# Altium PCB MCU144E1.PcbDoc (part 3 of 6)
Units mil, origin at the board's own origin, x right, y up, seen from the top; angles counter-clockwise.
Board outline 2755.9 x 2276.49 mil, 10 copper layers (Top Layer, L02_GND1, L03_SIG1, L04_GND2, L05_SIG2, L06_PWR, L07_GND3, L08_SIG3, L09_GND4, Bottom Layer), stack 60.4 mil thick; 257 components, 312 nets, 1297 pads, 831 vias.
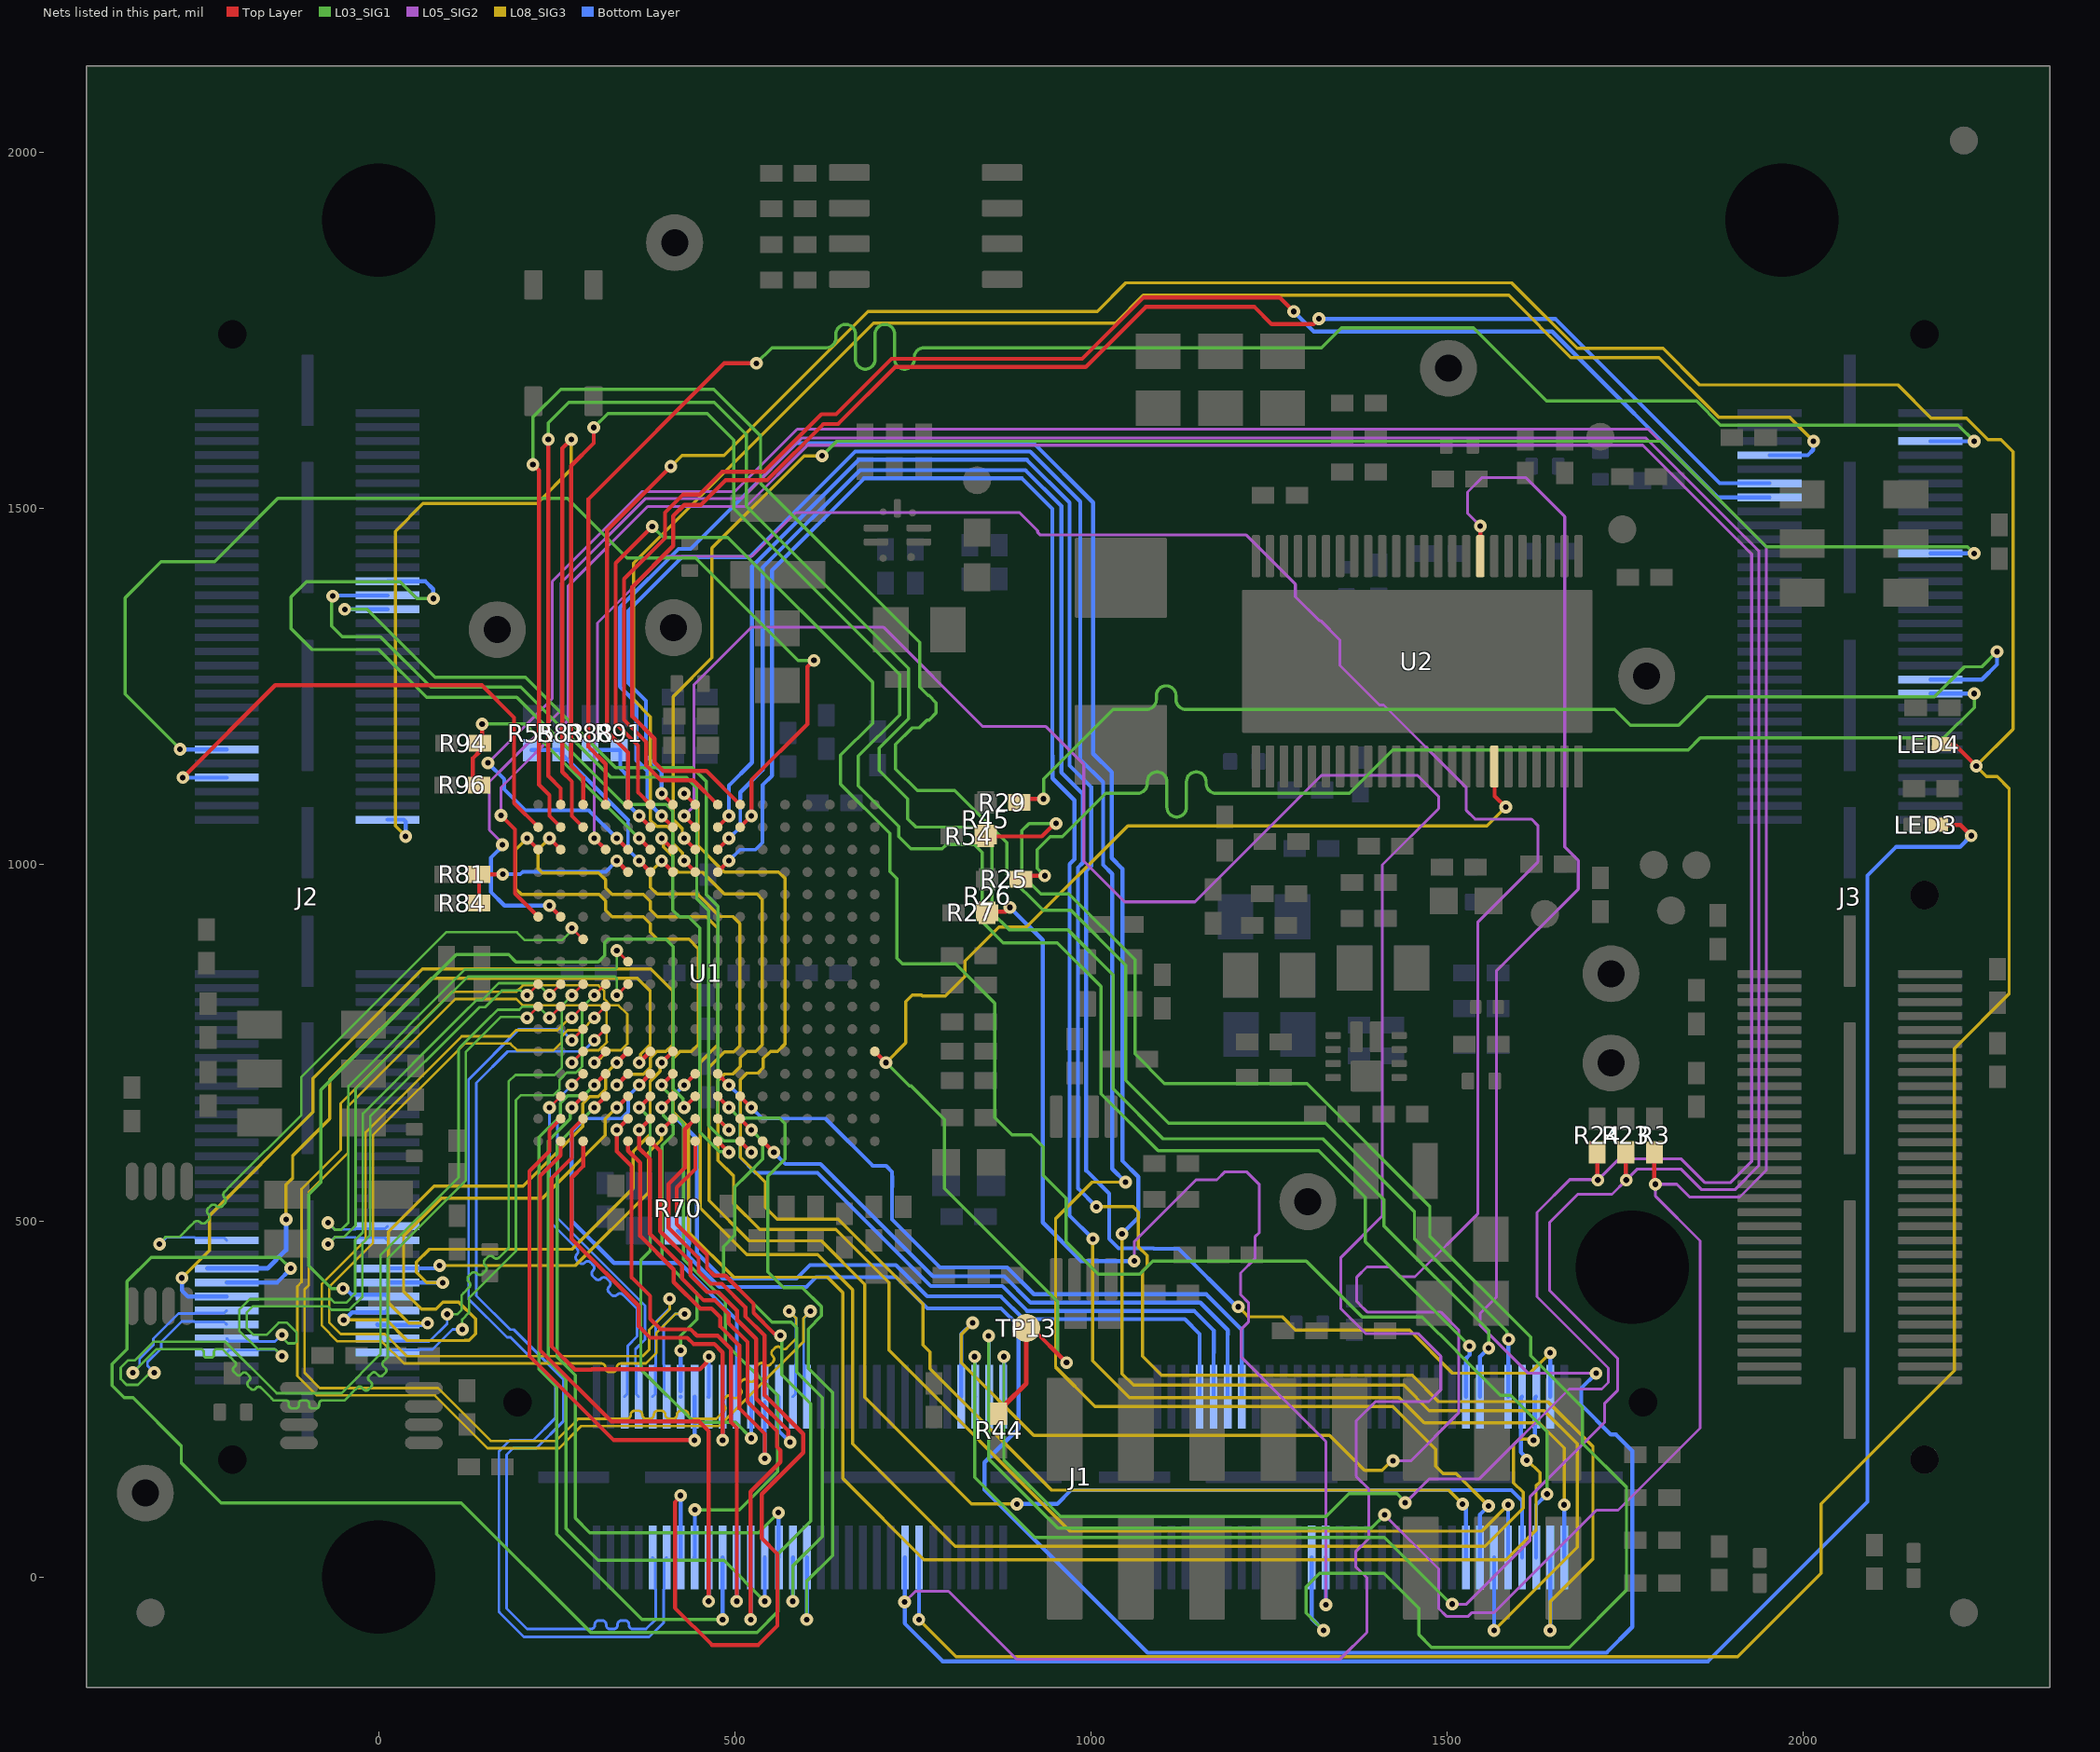
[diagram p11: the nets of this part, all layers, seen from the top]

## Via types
v1: diameter 18, hole 8, Top Layer to Bottom Layer, tented both sides, 777 vias
v2: diameter 19.68, hole 7.87, Top Layer to Bottom Layer, tented top, 54 vias

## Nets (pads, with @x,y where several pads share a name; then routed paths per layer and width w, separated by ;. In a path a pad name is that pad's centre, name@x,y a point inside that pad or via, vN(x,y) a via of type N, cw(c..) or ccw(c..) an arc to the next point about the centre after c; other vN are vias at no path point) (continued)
MCU_ADCIN_A10A11_P: J2.100 U1.G3 | length 960.5
  Top Layer w3.7: v1(271.28,911.2) U1.G3@287.03,895.46
  L03_SIG1 w3.5: v1(-307.61,467.54) -307.61,469.18 -299.35,477.44 -279.7,477.44 -271.97,485.17 -266.24,490.9 -258.8,498.35 cw(c-254.79,494.34) -250.78,498.35 -250.45,498.02 ccw(c-246.44,502.03) -242.43,498.02 -239,501.46 ccw(c-243.01,505.47) -239,509.48 -239.32,509.8 cw(c-235.31,513.81) -239.32,517.82 -235.89,521.26 cw(c-231.88,517.25) -227.87,521.26 -227.54,520.93 ccw(c-223.53,524.94) -219.52,520.93 -216.09,524.37 ccw(c-220.1,528.38) -216.09,532.39 -216.41,532.71 cw(c-212.4,536.72) -216.41,540.73 -208.07,549.07 -108.46,648.68 -108.46,702.12 94.74,905.33 159.9,905.33 193.9,905.33 204.94,894.29 257.51,894.29 274.42,911.2 v1(271.28,911.2)
  Bottom Layer w3.7: v1(-307.61,467.54) -298.11,477.04 -269.75,477.04 -258.53,477.04 -257.69,476.2 -216.69,476.2 J2.100@-213.19,472.7
MCU_ADCIN_A12A13_N: J2.110 U1.K1 | length 1321.3
  Top Layer w3.7: v1(208.29,785.22) U1.K1@224.04,800.97
  L03_SIG1 w3.5: v1(-345,287) -312,320 -278.92,320 -266.81,320 -259.71,320 -249.77,320 cw(c-249.77,315.74) -245.51,315.74 -245.51,312.26 ccw(c-241.25,312.26) -241.25,308 -235.57,308 ccw(c-235.57,312.26) -231.31,312.26 -231.31,315.74 cw(c-227.05,315.74) -227.05,320 -219.42,320 -213.57,314.15 -208.55,309.13 -201.52,302.1 cw(c-204.54,299.09) -201.52,296.07 -203.28,294.32 ccw(c-200.27,291.31) -203.28,288.3 -199.26,284.28 ccw(c-196.25,287.29) -193.24,284.28 -191.48,286.03 cw(c-188.47,283.02) -185.46,286.03 -181.44,282.02 cw(c-184.45,279.01) -181.44,275.99 -183.2,274.24 ccw(c-180.18,271.23) -183.2,268.21 -179.18,264.2 ccw(c-176.17,267.21) -173.16,264.2 -171.4,265.95 cw(c-168.39,262.94) -165.38,265.95 -165.13,265.7 -150.35,250.93 -147.36,247.94 -140.26,247.94 -130.32,247.94 cw(c-130.32,243.68) -126.06,243.68 -126.06,241.2 ccw(c-121.8,241.2) -121.8,236.94 -116.12,236.94 ccw(c-116.12,241.2) -111.86,241.2 -111.86,243.68 cw(c-107.6,243.68) -107.6,247.94 -101.92,247.94 cw(c-101.92,243.68) -97.66,243.68 -97.66,241.2 ccw(c-93.4,241.2) -93.4,236.94 -87.72,236.94 ccw(c-87.72,241.2) -83.46,241.2 -83.46,243.68 cw(c-79.2,243.68) -79.2,247.94 -69.26,247.94 -65,247.94 -48.61,247.94 -47.89,247.94 -41.67,254.16 -36.65,259.18 -29.62,266.21 cw(c-26.61,263.19) -23.6,266.21 -20.43,263.04 ccw(c-17.42,266.05) -14.4,263.04 -10.39,267.05 ccw(c-13.4,270.07) -10.39,273.08 -13.55,276.25 cw(c-10.54,279.26) -13.55,282.27 -9.54,286.29 cw(c-6.53,283.28) -3.51,286.29 -0.35,283.12 ccw(c2.67,286.13) 5.68,283.12 9.7,287.14 ccw(c6.68,290.15) 9.7,293.16 6.53,296.33 cw(c9.54,299.34) 6.53,302.35 10.04,305.87 12.82,308.64 12.82,447.24 122.4,556.82 122.4,737.4 171.36,786.36 198.5,786.36 199.65,785.22 v1(208.29,785.22)
  Bottom Layer w3.7: v1(-345,287) -335.5,296.5 -335.5,306.34 -316.2,325.63 -316.2,334.58 -280.86,369.93 -258.53,369.93 -257.69,370.77 -216.69,370.77 J2.110@-213.19,374.27
MCU_ADCIN_A12A13_P: J2.112 U1.K2 | length 1321.6
  Top Layer w3.7: v1(239.79,785.22) U1.K2@255.53,800.97
  L03_SIG1 w3.5: v1(-315,287) -320.82,287 -337.92,269.9 -353.9,269.9 -362.1,278.1 -362.1,294.08 -352.08,304.1 -342.32,304.1 -316.22,330.2 -215.2,330.2 -143.14,258.14 -52.11,258.14 2.62,312.87 2.62,451.47 112.2,561.05 112.2,741.62 115.09,744.51 151.16,780.58 167.14,796.56 197.57,796.56 201.98,800.97 224.04,800.97 v1(239.79,785.22)
  Bottom Layer w3.7: v1(-315,287) -324.5,296.5 -324.5,301.78 -305.2,321.08 -305.2,330.03 -276.3,358.93 -258.53,358.93 -257.69,358.09 -216.69,358.09 J2.112@-213.19,354.59
MCU_ADCIN_A14A15_N: J1.90 U1.M4 | length 2014.2
  Top Layer w3.7: v1(302.78,722.23) U1.M4@318.53,737.98
  L08_SIG3 w3.5: v1@298.55,722.23 v1(302.78,722.23) 304.94,722.23 311.53,728.81 ; 311.99,728.36 323.25,739.62 340.11,739.62 349.09,748.6 349.09,790.34 336.82,802.62 325.78,802.62 316.88,811.52 316.88,822.56 308.62,830.82 202.45,830.82 193.48,821.85 103.42,821.85 -53.29,665.13 -53.29,599.71 -108.2,544.8 -108.2,414.22 -114.2,408.22 -114.2,282.37 -86.83,255 79,255 153,181 253.42,181 284.42,212 478,212 596.38,330.38 596.38,363.33 v1(606.28,373.23)
  Bottom Layer w3.7: J1.90@597.62,252.13 597.47,252.28 597.47,297.81 596.78,298.51 596.78,363.73 v1(606.28,373.23)
MCU_ADCIN_A14A15_P: J1.92 U1.M3 | length 2055.5
  Top Layer w3.7: v1(271.28,722.23) U1.M3@287.03,737.98
  L08_SIG3 w3.5: v1(271.28,722.23) 288.68,739.62 308.83,739.62 320,750.79 ; 320.17,752.11 320.17,750.97 320,750.79 ; v1(576.28,373.23) 586.18,363.33 586.18,334.6 573.01,321.43 cw(c569,325.44) 564.99,321.43 564.52,321.9 ccw(c560.51,317.89) 556.5,321.9 553.07,318.46 ccw(c557.08,314.45) 553.07,310.44 553.53,309.98 cw(c549.52,305.97) 553.53,301.96 550.1,298.52 cw(c546.09,302.53) 542.08,298.52 541.61,298.99 ccw(c537.6,294.98) 533.59,298.99 530.16,295.55 ccw(c534.16,291.54) 530.16,287.53 530.62,287.07 cw(c526.61,283.06) 530.62,279.05 527.19,275.61 cw(c523.18,279.62) 519.17,275.61 518.7,276.08 ccw(c514.69,272.07) 510.68,276.08 507.25,272.64 ccw(c511.25,268.63) 507.25,264.62 507.71,264.16 cw(c503.7,260.15) 507.71,256.14 504.28,252.7 cw(c500.27,256.71) 496.26,252.7 495.79,253.17 ccw(c491.78,249.16) 487.77,253.17 484.33,249.73 ccw(c488.34,245.72) 484.33,241.71 484.8,241.25 cw(c480.79,237.24) 484.8,233.23 473.78,222.2 440.54,222.2 cw(c440.54,227.87) 434.87,227.87 ccw(c429.2,227.87) 429.2,233.54 424.34,233.54 ccw(c424.34,227.87) 418.67,227.87 cw(c413,227.87) 413,222.2 408.14,222.2 cw(c408.14,227.87) 402.47,227.87 ccw(c396.8,227.87) 396.8,233.54 391.94,233.54 ccw(c391.94,227.87) 386.27,227.87 cw(c380.6,227.87) 380.6,222.2 375.74,222.2 cw(c375.74,227.87) 370.07,227.87 ccw(c364.4,227.87) 364.4,233.54 359.54,233.54 ccw(c359.54,227.87) 353.87,227.87 cw(c348.2,227.87) 348.2,222.2 280.2,222.2 249.2,191.2 157.22,191.2 83.22,265.2 -82.6,265.2 -104,286.6 -104,404 -98,410 -98,540.57 -46.08,592.49 -43.09,595.48 -43.09,660.91 107.65,811.65 193.35,811.65 202.38,802.62 311.35,802.62 320,793.97 320,750.79
  Bottom Layer w3.7: v1(576.28,373.23) 585.78,363.73 585.78,298.53 584.94,297.69 J1.92@584.94,256.69 ; J1.92@581.44,253.19 J1.92@584.94,256.69 ; 585.78,298.51 585.09,297.81 585.09,256.84 J1.92@584.94,256.69
MCU_ADCIN_B0B1_N: J1.114 U1.N3 | length 526.7
  Top Layer w3.7: v1(271.28,690.73) U1.N3@287.03,706.48
  Bottom Layer w3.7: v1(271.28,690.73) 255.53,674.98 255.53,643.41 250.74,638.61 250.74,504.26 373.89,381.11 373.89,333.34 360.56,320.01 360.56,298.53 361.4,297.69 361.4,256.69 J1.114@364.9,253.19
MCU_ADCIN_B0B1_P: J1.116 U1.P2 | length 527.2
  Top Layer w3.7: v1(239.79,659.24) U1.P2@255.53,674.98
  Bottom Layer w3.7: 239.74,627.36 239.74,499.71 271.38,468.07 278.42,461.02 cw(c274.46,457.06) 278.42,453.1 278.16,452.84 ccw(c282.12,448.88) 278.16,444.92 281.55,441.53 ccw(c285.51,445.49) 289.47,441.53 289.73,441.79 cw(c293.69,437.83) 297.65,441.79 301.05,438.4 cw(c297.09,434.44) 301.05,430.48 300.79,430.22 ccw(c304.75,426.26) 300.79,422.3 304.18,418.9 ccw(c308.14,422.86) 312.1,418.9 312.36,419.16 cw(c316.32,415.2) 320.28,419.16 323.67,415.77 cw(c319.71,411.81) 323.67,407.85 323.41,407.59 ccw(c327.37,403.63) 323.41,399.67 326.81,396.28 ccw(c330.77,400.24) 334.73,396.28 334.99,396.54 cw(c338.95,392.58) 342.91,396.54 344.6,394.84 362.89,376.55 362.89,337.9 349.56,324.57 349.56,298.53 348.72,297.69 348.72,256.69 J1.116@345.22,253.19 ; 239.79,627.36 v1(239.79,659.24)
MCU_ADCIN_B2B3_N: J1.109 U1.L3 | length 1403.2
  Top Layer w3.7: v1(271.28,753.72) U1.L3@287.03,769.47
  Bottom Layer w3.7: v1(271.28,753.72) 255.69,769.32 197.02,769.32 126.21,698.5 126.21,390.41 180.15,336.47 185.15,336.47 248.04,273.58 248.04,223.16 216.99,192.12 184.36,192.12 168.74,176.5 168.74,-48.74 171.96,-51.96 204,-84 380,-84 399.93,-64.07 399.93,-17.75 400.77,-16.91 400.77,24.09 J1.109@404.27,27.59
MCU_ADCIN_B2B3_P: J1.111 U1.L4 | length 1400.5
  Top Layer w3.7: v1(302.78,753.72) U1.L4@318.53,769.47
  Bottom Layer w3.7: v1(302.78,753.72) 287.03,737.98 181.24,737.98 137.21,693.95 137.21,394.96 184.71,347.47 189.71,347.47 259.04,278.14 259.04,218.61 221.55,181.12 188.92,181.12 179.74,171.94 179.74,-44.18 208.56,-73 280.84,-73 287.44,-73 297.84,-73 ccw(c297.84,-67.4) 303.44,-67.4 303.44,-66.6 cw(c309.04,-66.6) 309.04,-61 313.84,-61 cw(c313.84,-66.6) 319.44,-66.6 319.44,-67.4 ccw(c325.04,-67.4) 325.04,-73 329.84,-73 ccw(c329.84,-67.4) 335.44,-67.4 335.44,-66.6 cw(c341.04,-66.6) 341.04,-61 345.84,-61 cw(c345.84,-66.6) 351.44,-66.6 351.44,-67.4 ccw(c357.04,-67.4) 357.04,-73 367.44,-73 375.44,-73 388.93,-59.51 388.93,-17.75 388.09,-16.91 388.09,24.09 J1.111@384.59,27.59
MCU_ADCIN_B4B5_N: J1.110 U1.K3 | length 1405.5
  Top Layer w3.7: v1(271.28,785.22) U1.K3@287.03,800.97
  L08_SIG3 w3.5: v1(271.28,785.22) 268.41,785.22 251.02,767.82 192.93,767.82 184.31,759.2 116.53,759.2 -18.2,624.47 -18.2,473.23 -76.71,414.71 -79.7,411.72 -79.7,353.09 -57.61,331 4.58,331 35.65,299.93 312.56,299.93 cw(c312.56,294.26) 318.23,294.26 318.23,293.6 ccw(c323.9,293.6) 323.9,287.93 328.76,287.93 ccw(c328.76,293.6) 334.43,293.6 334.43,294.26 cw(c340.1,294.26) 340.1,299.93 374.93,299.93 390.04,315.04 390.04,342.96 416.58,369.5 v1(429.58,369.5) v1@430.58,369.5
  Bottom Layer w3.7: J1.110@404.27,253.19 400.62,256.84 400.62,297.81 399.93,298.51 399.93,353.79 415.64,369.5 v1(429.58,369.5)
MCU_ADCIN_B4B5_P: J1.112 U1.K4 | length 1405
  Top Layer w3.7: v1(302.78,785.22) U1.K4@318.53,800.97
  L08_SIG3 w3.5: v1(302.78,785.22) 285.38,767.82 265.44,767.82 257.18,759.56 257.18,751.18 245.63,739.62 194.38,739.62 185,749 120.75,749 -8,620.25 -8,469 -69.5,407.5 -69.5,357.32 -53.38,341.2 8.8,341.2 39.87,310.13 370.7,310.13 379.84,319.26 379.84,347.19 382.83,350.17 408.5,375.85 v1@408.5,389.85
  Bottom Layer w3.7: J1.112@384.59,253.19 388.24,256.84 388.24,297.81 388.93,298.51 388.93,358.35 408.37,377.79 v1(408.37,390.72)
MCU_ADCIN_B6B7_N: J2.97 U1.H5 | length 809.9
  Top Layer w3.7: v1(334.27,879.71) U1.H5@350.02,863.96
  L03_SIG1 w3.5: v1(-71.17,497.54) -61.27,487.64 -52.72,487.64 -42.46,497.9 -42.46,689.52 121.21,853.2 159.9,853.2 331.81,853.2 334.27,855.66 v1(334.27,879.71)
  Bottom Layer w3.7: v1(-71.17,497.54) -61.67,488.04 -39.59,488.04 -32.93,488.04 -32.09,488.88 8.91,488.88 J2.97@12.41,492.38
MCU_ADCIN_B6B7_P: J2.99 U1.J5 | length 809.6
  Top Layer w3.7: v1(334.27,816.72) U1.J5@350.02,832.46
  L03_SIG1 w3.5: v1(-71.17,467.54) -61.27,477.44 -48.5,477.44 -32.26,493.67 -32.26,685.3 125.44,843 159.9,843 331.81,843 334.27,840.54 v1(334.27,816.72)
  Bottom Layer w3.7: v1(-71.17,467.54) -61.67,477.04 -44.15,477.04 -32.93,477.04 -32.09,476.2 8.91,476.2 J2.99@12.41,472.7
MCU_ADCIN_B12B13_N: J2.114 U1.J1 | length 985.1
  Top Layer w3.7: v1(208.29,816.72) U1.J1@224.04,832.46
  L03_SIG1 w3.5: v1(-135.86,340.06) -135.86,336.86 -127,328 -118,328 -115,331 -115,343.38 -128.78,357.16 -140.22,357.16 -157.38,340 -175.58,340 -185.2,349.62 -185.2,371.46 -176.71,379.96 -70.96,379.96 -66.11,375.11 -41.28,375.11 -22.7,393.69 -22.7,469.07 -11.86,479.91 -11.86,646.61 141.68,800.15 149.55,800.15 173.01,823.62 193.55,823.62 193.67,823.73 198.93,823.73 205.94,816.72 v1(208.29,816.72)
  Bottom Layer w3.7: J2.114@-213.19,334.9 -209.69,331.4 -168.69,331.4 -167.85,330.56 -145.36,330.56 v1(-135.86,340.06)
MCU_ADCIN_B12B13_P: J2.116 U1.J2 | length 989.6
  Top Layer w3.7: v1(239.79,816.72) U1.J2@255.53,832.46
  L03_SIG1 w3.5: v1(-135.86,310.06) -145.76,319.96 -169.96,319.96 -195.4,345.4 -195.4,375.69 -180.93,390.16 -66.73,390.16 -61.89,385.31 -45.5,385.31 -32.9,397.92 -32.9,473.29 -22.06,484.13 -22.06,650.83 116.79,789.68 137.46,810.35 145.32,810.35 168.79,833.82 189.33,833.82 189.44,833.93 222.57,833.93 236.65,819.85 236.65,816.72 v1(239.79,816.72)
  Bottom Layer w3.7: J2.116@-213.19,315.22 -209.69,318.72 -168.69,318.72 -167.85,319.56 -145.36,319.56 v1(-135.86,310.06)
MCU_ADCIN_B16B17_N: J2.113 U1.J3 | length 720.7
  Top Layer w3.7: v1(271.28,816.72) U1.J3@287.03,832.46
  L03_SIG1 w3.5: v1(96.12,368.95) 110.13,368.95 116.6,375.42 116.6,396.03 119.48,398.9 126.92,406.35 ccw(c122.91,410.36) 126.92,414.37 126.46,414.83 cw(c130.47,418.84) 126.46,422.85 129.89,426.29 cw(c133.9,422.28) 137.91,426.29 138.38,425.82 ccw(c142.39,429.83) 146.4,425.82 149.83,429.26 ccw(c145.82,433.27) 149.83,437.28 149.37,437.74 cw(c153.38,441.75) 149.37,445.76 152.8,449.2 cw(c156.81,445.19) 160.82,449.2 161.29,448.73 ccw(c165.3,452.74) 169.31,448.73 176.75,456.18 182.48,461.9 182.48,695.48 192,705 246.74,705 257.18,715.44 257.18,802.62 v1(271.28,816.72)
  Bottom Layer w3.7: J2.113@12.41,334.9 15.91,331.4 56.91,331.4 57.75,330.56 71.17,330.56 96.12,355.51 v1(96.12,368.95)
MCU_ADCIN_B16B17_P: J2.115 U1.J4 | length 720.9
  Top Layer w3.7: v1(302.78,816.72) U1.J4@318.53,832.46
  L03_SIG1 w3.5: v1(117.34,347.73) 117.34,361.73 126.8,371.2 126.8,391.8 192.68,457.68 192.68,669.68 199.63,676.63 245.63,676.63 253.89,684.89 253.89,697.72 264.29,708.13 277.12,708.13 285.68,716.68 285.68,799.62 v1(302.78,816.72)
  Bottom Layer w3.7: J2.115@12.41,315.22 15.91,318.72 56.91,318.72 57.75,319.56 75.73,319.56 103.9,347.73 v1(117.34,347.73)
MCU_ADCIN_C0: J1.106 U1.R2 | length 693.3
  Top Layer w5.66: U1.R2@255.53,643.49 239.79,627.74 239.79,597.85 211.67,569.74 211.67,310.55 330.05,192.17 v1(443.51,192.17)
  Bottom Layer w5.66: v1(443.51,192.17) 443.57,192.23 443.57,253.12 J1.106@443.64,253.19 J1.106@443.83,253.38
MCU_ADCIN_C1: J1.103 U1.T2 | length 889.7
  Top Layer w5.66: U1.T2@255.53,611.99 255.53,592.19 226.76,563.42 226.76,318.43 326.76,218.43 449.77,218.43 463.24,204.96 v1(463.24,-34.06)
  Bottom Layer w5.66: v1(463.24,-34.06) 463.33,-33.97 J1.103@463.33,27.59
MCU_ADCIN_C2: J1.101 U1.N4 | length 1078.2
  Top Layer w5.66: v1(302.78,690.73) U1.N4@318.53,706.48
  L03_SIG1 w4.5: v1(302.78,690.73) 287.98,675.93 265.35,675.93 255,665.58 255,647.17 225.27,617.44 225.27,560.65 225.27,291.7 250.14,266.82 250.14,59.97 369.78,-59.66 v1(482.82,-59.66)
  Bottom Layer w5.66: v1(482.82,-59.66) 482.95,-59.54 J1.101@482.95,27.53
MCU_ADCIN_C3: J2.111 U1.M5 | length 712.6
  Top Layer w5.66: v1(334.27,722.23) U1.M5@350.02,737.98
  L08_SIG3 w4.5: v1@69.67,356.46 42.54,356.46 14,385 14,485 77.91,548.91 202.91,548.91 286.59,632.59 286.59,664.71 296.43,674.55 308.25,674.55 318.52,684.82 318.52,706.48 v1(334.27,722.23)
  Bottom Layer w5.66: J2.111@-2,354.59 -1.55,354.14 65.23,354.14 67.55,356.46 v1@69.67,356.46
  other v1: 68.67,356.46
MCU_ADCIN_C4: J2.109 U1.P5 | length 901.5
  Top Layer w5.66: v1(334.27,659.24) U1.P5@350.02,674.98
  L08_SIG3 w4.5: v1(-49,361) 11,361 40,332 120.88,332 121.3,332.42 126.75,332.42 136,341.67 136,362.28 112.28,386 90.41,386 80.41,376 60,376 35,401 35,479 88,532 230,532 318.09,620.09 318.09,643.05 v1(334.27,659.24)
  Bottom Layer w5.66: v1(-49,361) -47.82,361 -37.21,371.6 9.74,371.6 J2.109@12.41,374.27
MCU_ADCIN_C5: J2.108 U1.N5 | length 1228.5
  Top Layer w5.66: v1(334.27,690.73) U1.N5@350.02,706.48
  L08_SIG3 w4.5: v1(-276.21,420.04) -237.66,458.59 -237.66,507.34 -92,653 -92,700 61.54,853.54 382.1,853.54 412.58,823.06 412.58,747.38 403.14,737.94 390.76,737.94 381.48,728.67 381.48,715.72 371.81,706.04 349.59,706.04 v1(334.27,690.73)
  Bottom Layer w5.66: v1(-276.21,420.04) -276.21,402.47 -267.69,393.96 J2.108@-213.19,393.96
MCU_ADCIN_C11: J2.107 U1.P8 | length 1243.1
  Top Layer w5.66: v1(428.76,659.24) U1.P8@444.51,674.98
  L03_SIG1 w4.5: v1(-50,405) -66.18,405 -98,436.82 -98,537 -81,554 -81,684 109,874 182.43,874 192.71,863.72 308.45,863.72 317.47,872.74 317.47,881.81 317.28,881.99 317.28,891.28 321.71,895.71 344.17,895.71 344.41,895.47 403.16,895.47 413.45,885.18 413.45,685.54 427.36,671.63 427.36,660.64 v1(428.76,659.24)
  Bottom Layer w5.66: v1(-50,405) -46.66,405 -38.29,396.63 9.74,396.63 J2.107@12.41,393.96
MCU_ADCIN_C12: J1.107 U1.R8 | length 1273.1
  Top Layer w5.66: v1(423.87,114.55) 423.87,112.99 415.94,105.06 415.94,-43.37 467.93,-95.36 532.85,-95.36 559.81,-68.41 559.81,32.53 537.88,54.45 537.88,116.5 596.14,174.77 596.14,200.86 541.66,255.34 541.66,339.17 514.74,366.09 514.74,378.82 481.81,411.76 466.18,411.76 449.18,428.76 449.18,448.02 406.84,490.36 406.84,551.66 429.79,574.61 429.79,628.77 U1.R8@444.51,643.49
  Bottom Layer w5.66: v1(423.87,114.55) v1(423.87,114.55) 423.91,27.63 J1.107@423.96,27.59
MCU_ADCIN_C13: J2.106 U1.T8 | length 2384.8
  Top Layer w5.66: U1.T8@444.51,611.99 444.51,572.84 418.5,546.83 418.5,495.19 460.84,452.85 460.84,433.59 471.01,423.42 486.64,423.42 526.4,383.65 526.4,370.92 555.96,341.36 561.64,341.36 v1(564,339)
  L03_SIG1 w4.5: v1(-123.46,433.49) -139.05,449.07 -319.3,449.07 -353.24,415.13 -353.24,320.04 -374.02,299.26 -374.02,268.8 -357.22,252 -345,252 -277,184 -277,160.11 -220.89,104 116,104 297.98,-77.98 531.02,-77.98 561,-48 561,33 606.61,78.61 606.61,243.39 566,284 v1@566,336
  Bottom Layer w5.66: J2.106@-213.19,413.64 -142.31,413.64 v1@-122.96,432.99
MCU_ADCIN_C16: J1.105 U1.N7 | length 837.8
  Top Layer w5.66: v1(397.27,690.73) U1.N7@413.01,706.48
  L03_SIG1 w4.5: v1(397.27,690.73) 397.27,689.03 405.26,681.03 ; 405.26,681 413.02,673.24 413.02,665.76 413.01,650.99 425,639 428.15,635.85 428.15,540.12 428.06,540.03 428.06,446.08 487,387.14 487,328 560,255 560,148 506.48,94.48 v1(444.08,94.48)
  Bottom Layer w5.66: J1.105@443.52,27.46 J1.105@443.64,27.59 443.86,27.81 443.86,94.26 v1(444.08,94.48)
MCU_ADCIN_C17: J1.108 U1.P7 | length 463.9
  Top Layer w5.66: v1(397.27,659.24) U1.P7@413.01,674.98
  L03_SIG1 w4.5: v1(397.27,659.24) 399.44,657.06 399.44,648.24 413.57,634.11 413.57,621.71 397.53,605.66 397.53,560.65 397.53,447.47 446.89,398.1 446.89,361.9 423.94,338.94 v1@423.94,320.07
  Bottom Layer w5.66: J1.108@423.9,253.14 J1.108@423.96,253.19 ; J1.108@423.94,261.01 v1@423.94,320.07
  other v1: 423.94,318.07
MCU_ADCIN_D0: J1.104 U1.R3 | length 642.1
  Top Layer w5.66: U1.R3@287.03,643.49 271.28,627.74 271.28,588.33 242.55,559.6 242.55,324.12 275.36,291.32 299.07,291.32 299.36,291.61 450.9,291.61 459.87,300.58 459.87,302.26 463.72,306.11 v1(463.72,309.45)
  Bottom Layer w5.66: J1.104@463.33,253.19 463.52,253.38 463.52,311.94 v1@463.72,312.14
MCU_ADCIN_D1: J1.102 U1.T3 | length 622.7
  Top Layer w5.66: U1.T3@287.03,611.99 287.03,576.68 271,560.65 271,474.68 364.97,380.71 364.97,352.14 381.12,336 433.22,336 441.94,327.28 471.1,327.28 482.9,315.48 v1(482.9,192.27)
  Bottom Layer w5.66: v1@482.97,192.34 J1.102@483.01,253.19 J1.102@483.01,253.19
MCU_ADCIN_D2: J1.99 U1.R5 | length 857.5
  Top Layer w5.66: U1.R5@350.02,643.49 v1(334.27,627.74) 334.27,597.59 354.91,576.95 354.91,420.86 381.09,394.68 381.09,362.56 395.98,347.66 438.05,347.66 446.77,338.94 475.93,338.94 494.57,320.31 494.57,217.44 502.91,209.09 502.91,-33.76 v1(502.61,-34.06)
  Bottom Layer w5.66: v1(502.61,-34.06) 502.7,-33.97 J1.99@502.7,27.59
MCU_ADCIN_D3: J1.97 U1.R6 | length 905.5
  Top Layer w5.66: U1.R6@381.52,643.49 v1(365.77,627.74) 365.77,602 380.77,587 380.77,481.78 425.86,436.68 425.86,419.1 456.52,388.44 472.15,388.44 491.42,369.16 491.42,356.43 517.88,329.97 517.88,246.14 559,205.02 559,182.78 564,177.78 564,161.48 522.19,119.68 v1(522.19,-59.66)
  Bottom Layer w5.66: v1(522.19,-59.66) 522.32,-59.54 J1.97@522.32,27.53
MCU_ADCIN_D10: J1.100 U1.N6 | length 679.5
  Top Layer w5.66: v1(365.77,690.73) U1.N6@381.52,706.48
  Bottom Layer w5: 289.3,643.67 340.63,643.67 350.27,653.31 350.27,675.23 v1(365.77,690.73)
  Bottom Layer w5.66: 289.3,643.67 271,625.37 271,500.29 330.29,441 422.87,441 502.91,360.96 502.91,253.4 J1.100@502.7,253.19
MCU_ADCIN_D11: J1.98 U1.P6 | length 655
  Top Layer w5.66: v1(365.77,659.24) U1.P6@381.52,674.98
  L03_SIG1 w4.5: v1(365.77,659.24) 381.08,643.92 381.08,457.83 368,444.75 368,292 443,217 501.06,217 v1(523.07,194.99)
  Bottom Layer w5.66: J1.98@522.38,253.19 523.07,252.53 v1(523.07,194.99)
MCU_ADCIN_D12: J2.105 U1.M7 | length 697.2
  Top Layer w5.66: v1(397.27,722.23) U1.M7@413.01,737.98
  L08_SIG3 w4.5: v1(90.04,413.35) 67.65,413.35 53,428 53,442 71.27,460.27 271.27,460.27 357,546 357,560.65 357,597.31 381.08,621.4 381.08,696.2 395.09,710.21 395.09,720.05 v1(397.27,722.23)
  Bottom Layer w5.66: J2.105@12.41,413.64 12.76,413.3 89.99,413.3 v1(90.04,413.35)
MCU_ADCIN_D13: J2.104 U1.M6 | length 1030.9
  Top Layer w5.66: v1(365.77,722.23) U1.M6@381.52,737.98
  L08_SIG3 w4.5: v1(-130,502) -130,551 -120.7,560.3 -120.7,591.3 -68.59,643.41 -68.59,698.41 73.92,840.92 363.23,840.92 381.08,823.06 381.08,747.38 367.95,734.24 367.95,724.4 v1(365.77,722.23)
  Bottom Layer w6.63: J2.104@-240.12,433.54 -155.72,433.54 -130,459.27 v1(-130,502)
MCU_ADCIN_D16: J2.103 U1.R7 | length 528.4
  Top Layer w5.66: v1(397.27,627.74) U1.R7@413.01,643.49
  L08_SIG3 w4.5: v1(85.64,437.35) 276.35,437.35 378.63,539.63 378.63,560.65 378.63,595.84 397.27,614.48 v1(397.27,627.74)
  Bottom Layer w5.66: J2.103@12.41,433.33 81.61,433.33 v1(85.64,437.35)
MCU_ADCIN_D17: R70.1 U2.32 | length 3882.1
  Top Layer w5.66: U2.32@1546.52,1433.38 v1(1546.52,1475.73) v1@1546.52,1476.73
  L05_SIG2 w4: v1(1546.52,1475.73) 1528.69,1493.56 1528.69,1523.44 1549.15,1543.9 1610,1543.9 1665,1488.9 1665,1025 1683.98,1006.02 1683.98,965.85 1569,850.87 1569,393 1546,370 1546,353.89 1613.89,286 v1(1709,286)
  Bottom Layer w5.66: R70.1@420.17,486.31 435.04,471.44 435.04,450.47 478.18,407.33 600.46,407.33 614.13,421 726.58,421 770.44,377.15 873.85,377.15 898.45,352.55 898.45,208.82 850.55,160.93 850.55,122.68 908.63,64.6 1079.52,-106.29 1723.71,-106.29 1760,-70 1760,177 1737,200 1729.78,200 1688.17,241.61 1688.17,265.17 v1(1709,286)
MCU_ADCIN_E0: J1.95 U1.P3 | length 1020.3
  Top Layer w5.66: v1(271.28,659.24) U1.P3@287.03,674.98
  L03_SIG1 w4.5: v1(271.28,659.24) 269.11,657.06 269.11,643.42 237.89,612.21 237.89,560.65 237.89,303.45 263.27,278.08 263.27,68.33 308.3,23.3 484.61,23.3 v1(541.98,-34.06)
  Bottom Layer w5.66: v1(541.98,-34.06) 542.07,-33.97 J1.95@542.07,27.59
MCU_ADCIN_E1: J1.93 U1.P4 | length 999.3
  Top Layer w5.66: v1(302.78,659.24) U1.P4@318.53,674.98
  L03_SIG1 w4.5: v1(302.78,659.24) 250.52,606.98 250.52,560.65 250.52,308.68 275.89,283.31 275.89,82.75 296.2,62.44 533.3,62.44 v1(561.25,90.39)
  Bottom Layer w5.66: v1(561.25,90.39) 561.5,90.14 561.5,27.84 J1.93@561.75,27.59
MCU_ADCIN_E2: J1.96 U1.T5 | length 613.6
  Top Layer w5.66: U1.T5@350.02,611.99 350.02,598.75 366.97,581.8 366.97,479.09 414.2,431.86 414.2,414.27 451.69,376.78 467.32,376.78 479.76,364.33 479.76,351.6 506.22,325.14 506.22,237.05 542.08,201.19 v1(542.08,166.31)
  Bottom Layer w5.66: J1.96@542.07,253.19 J1.96@542.2,253.32 ; v1(542.08,166.31) J1.96@542.08,245.37
MCU_ADCIN_E3: J1.94 U1.T6 | length 583.3
  Top Layer w5.66: U1.T6@381.52,611.99 395.18,598.33 395.18,485.53 437.52,443.19 437.52,423.93 461.35,400.1 476.98,400.1 503.08,373.99 503.08,361.26 530,334.34 530,250.51 575.27,205.24 575.27,191.73 v1(577.58,189.41)
  Bottom Layer w5.66: J1.94@561.75,253.19 561.75,205.24 v1(577.58,189.41)
MCU_ADCIN_E10: J1.91 U1.R10 | length 865.5
  Top Layer w5.66: U1.R10@507.5,643.49 v1(523.25,627.74)
  L03_SIG1 w4.5: v1(523.25,627.74) 539,611.99 539,586.6 517.2,564.8 500.05,547.65 500.05,480.06 484,464.01 484,426 552.08,357.92 578.75,357.92 586.88,349.8 586.88,288.12 623,252 623,57.13 581.35,15.47 v1(581.35,-34.06)
  Bottom Layer w5.66: v1(581.35,-34.06) 581.44,-33.97 J1.91@581.44,27.59
MCU_ADCIN_E12: J1.89 U1.P9 | length 987.2
  Top Layer w5.66: U1.P9@476.01,674.98 v1(491.75,659.24)
  L03_SIG1 w4.5: v1(491.75,659.24) 506.47,644.52 562.48,644.52 570.53,636.47 570.53,586.99 546.42,562.88 546.42,428.42 568.37,406.48 594.86,406.48 621.59,379.75 621.59,366.89 603,348.3 603,293 637,259 637,30.2 600.93,-5.87 v1(600.93,-59.66)
  Bottom Layer w5.66: v1(600.93,-59.66) 601.06,-59.54 J1.89@601.06,27.53
MCU_AIO186: J1.54 U1.N8 | length 1135
  Top Layer w5.66: v1(428.76,690.73) U1.N8@444.51,706.48
  Bottom Layer w5: 418.01,643.99 413.26,648.74 413.26,675.23 v1(428.76,690.73)
  Bottom Layer w5.66: 418.01,643.99 446.43,615.57 446.43,572.5 446.7,572.24 446.7,455.3 483.01,418.99 586.46,418.99 605.54,438.08 726.08,438.08 769.95,394.21 873.28,394.21 905.42,362.07 1131.78,362.07 1152.55,341.3 1152.55,340.38 1152.42,340.25 J1.54@1152.42,253.19
MCU_AIO206: J2.27 U1.T10 | length 1307.5
  Top Layer w5.66: U1.T10@507.5,611.99 v1(523.25,596.24)
  L03_SIG1 w4.5: v1(-64.39,1377.23) -65.89,1375.73 -65.89,1335.29 -50.87,1320.27 2.27,1320.27 73.21,1249.33 199.67,1249.33 326,1123 431.78,1123 446.51,1108.27 446.51,952.81 463.41,935.9 463.41,633.86 485.03,612.24 507.25,612.24 v1(523.25,596.24)
  Bottom Layer w5.66: v1@-66.39,1377.23 -65.5,1378.13 J2.27@12.61,1378.13
MCU_AIO207: J2.25 U1.T9 | length 1536
  Top Layer w5.66: U1.T9@476.01,611.99 v1(491.75,596.24)
  L03_SIG1 w4.5: v1(77.06,1373.92) 53.89,1373.92 30.32,1397.49 -101.53,1397.49 -122.82,1376.2 -122.82,1331.64 -93.41,1302.23 -0.01,1302.23 67.21,1235 194,1235 344.53,1084.47 403.7,1084.47 411.99,1076.18 411.99,1075.62 412.98,1074.63 412.98,936.26 422.32,926.92 435.27,926.92 450.79,911.4 450.79,624.54 478.07,597.26 490.73,597.26 v1(491.75,596.24)
  Bottom Layer w5.66: J2.25@12.41,1398.01 12.5,1397.92 65.74,1397.92 76.69,1386.97 76.69,1374.29 v1(77.06,1373.92)
MCU_AIO209: J2.29 U1.R9 | length 1192.7
  Top Layer w5.66: U1.R9@476.01,643.49 v1(491.75,627.74)
  L03_SIG1 w4.5: v1(-47.57,1358.7) -16.39,1358.7 79.17,1263.14 205.86,1263.14 332.69,1136.31 440.53,1136.31 460.23,1116.61 460.23,957.58 476.04,941.77 476.04,674.04 476,674 476,643.49 v1(491.75,627.74)
  Bottom Layer w5.66: v1(-47.57,1358.7) -47.43,1358.84 -47.25,1358.67 12.38,1358.67 J2.29@12.61,1358.44
MCU_AIO211: J1.52 U1.N9 | length 988.8
  Top Layer w5.66: U1.N9@476.01,706.48 v1(491.75,690.73)
  Bottom Layer w5: v1(491.75,690.73) 507.75,674.74 507.75,588.91 529.07,567.59
  Bottom Layer w5.66: 529.07,567.59 615.95,567.59 775.08,408.47 875.51,408.47 910.25,373.73 1144.72,373.73 1172.2,346.25 1172.2,314.84 1172.11,314.75 J1.52@1172.11,253.19
MCU_AIO212: J1.48 U1.P10 | length 973.3
  Top Layer w5.66: U1.P10@507.5,674.98 v1(523.25,659.24)
  Bottom Layer w5: v1(523.25,659.24) 538.75,643.74 627.22,643.74 627.75,643.2
  Bottom Layer w5.66: 627.75,643.2 693.67,577.28 712.4,577.28 720.76,568.91 720.76,562.56 721.05,562.28 721.05,547.51 720.76,547.22 720.76,502.12 788.07,434.81 882.14,434.81 919.91,397.05 1161.74,397.05 1211.57,347.22 1211.57,314.84 1211.48,314.75 J1.48@1211.48,253.19
MCU_AIO213: J1.50 U1.T11 | length 856.4
  Top Layer w5.66: U1.T11@539,611.99 v1(554.75,596.24)
  Bottom Layer w5.66: v1(554.75,596.24) 571.03,579.96 579.43,579.96 579.48,579.91 620.13,579.91 639.39,560.65 777.78,422.26 878.21,422.26 915.08,385.39 1153.35,385.39 1191.92,346.82 1191.92,340.38 1191.79,340.25 J1.50@1191.79,253.19
MCU_CANRX: J1.37 R45.1 R54.1 | length 2452.1
  Top Layer w5.66: R45.1@851.9,1040.34 852.34,1039.9 930.9,1039.9 v1@950,1059
  L03_SIG1 w4.5: v1(951,1058) 913,1058 903,1048 903,986.02 929.66,959.35 968.99,959.35 1061.56,866.78 1061.56,734.53 1103.09,693 1303,693 1475.63,520.37 1475.63,478.2 1617,336.82 1617,311 1690,238 1690,188 1751.69,126.31 1751.69,-18.31 1671.33,-98.67 1477.88,-98.67 1460,-80.79 1460,-44.03 1410.97,5 1321,5 1302.2,-13.8 1302.2,-50.61 v1(1326.56,-74.97)
  Bottom Layer w5.66: J1.37@1309.9,27.59 1309.9,-58.31 v1(1326.56,-74.97)
MCU_CANTX: J1.35 R26.1 R27.1 | length 1622.5
  Top Layer w5.66: R26.1@857.42,931.32 857.42,934.24 880.44,934.24 v1(886.3,940.1)
  L05_SIG2 w4: v1(1060.6,443.71) 1060.6,470.79 1147.49,557.68 1176.54,557.68 1187.92,569.06 1218.39,569.06 1236.4,551.05 1236.4,483.83 1230.1,477.53 1230.1,446.96 1210,426.86 1210,396.41 1221,385.41 1221,358 1211,348 1211,309 1329.76,190.23 v1(1329.76,-38.78)
  Bottom Layer w5.66: v1(886.3,940.1) 932.17,894.23 932.17,497.83 986.29,443.71 v1(1060.6,443.71) ; J1.35@1329.59,27.59 1329.76,27.41 v1(1329.76,-38.78)
MCU_ERRORSTS: R44.2 TP13.1 U1.M16 U2.18 | length 1894.1
  Top Layer w5.66: U1.M16@696.48,737.98 v1(712.23,722.23) ; TP13.1@909.23,349.63 917.01,349.63 v1(965.59,301.05) ; U2.18@1566.21,1138.1 1566.57,1137.73 1566.57,1096.14 1566.94,1096.14 v1(1582.13,1080.96) ; v1@1581.95,1080.77 v1@1582.13,1080.59
  Top Layer w6.66: R44.2@870.64,229.47 870.64,233.41 879.12,241.89 909.23,272 TP13.1@909.23,349.63
  L03_SIG1 w4.5: v1(712.23,722.23) 744.97,689.48 747.52,689.48 794.3,642.7 794.3,545.44 953.21,386.54 953.21,312.64 964.79,301.05 v1(965.59,301.05)
  L08_SIG3 w4.5: v1(712.23,722.23) 740.05,750.05 740.05,808.07 749.02,817.04 761.98,817.04 763.22,815.79 795.68,815.79 823,843.11 823,865 870.67,912.67 909.67,912.67 1051.69,1054.69 1555.86,1054.69 1581.87,1080.69 1581.87,1081.22 v1(1582.13,1080.96)
MCU_ESC_RX1_DATA1: J3.80 R25.1 | length 1695.1
  Top Layer w5.66: R25.1@899.57,984.45 v1@934.82,984.45
  L03_SIG1 w4.5: v1(935.02,984.65) 924.39,995.27 924.39,1021.39 942.69,1039.69 959.69,1039.69 1020.52,1100.52 1063.07,1100.52 1065.32,1100.52 ccw(c1065.32,1114.27) 1079.07,1114.27 1079.07,1116.77 cw(c1092.82,1116.77) 1106.57,1116.77 1106.57,1080.93 ccw(c1120.32,1080.93) 1134.07,1080.93 1134.07,1116.77 cw(c1147.82,1116.77) 1161.57,1116.77 1161.57,1114.27 ccw(c1175.32,1114.27) 1175.32,1100.52 1200,1100.52 1362.72,1100.52 1423.55,1161.35 1838.41,1161.35 1855.07,1178 2197,1178 2239.84,1220.84 v1(2239.84,1240.36)
  Bottom Layer w5.66: J3.80@2178.19,1240.45 2239.75,1240.45 v1(2239.84,1240.36)
MCU_ESC_RX1_DATA2: J3.82 R29.1 | length 1658.1
  Top Layer w5.66: R29.1@899.15,1087.58 904.12,1092.55 v1(933.35,1092.55)
  L03_SIG1 w4.5: v1(933.35,1092.55) 933.35,1120.64 1031,1218.28 1075.76,1218.28 1078.01,1218.28 ccw(c1078.01,1232.03) 1091.76,1232.03 1091.76,1237.54 cw(c1105.51,1237.54) 1119.26,1237.54 1119.26,1232.03 ccw(c1133.01,1232.03) 1133.01,1218.28 1169.58,1218.28 1215,1218.28 1702.09,1218.28 1734.89,1218.28 1757.44,1195.72 1824.96,1195.72 1864.92,1235.68 2183.68,1235.68 2226,1278 2250.36,1278 v1(2271.71,1299.34)
  Bottom Layer w5.66: J3.82@2178.19,1260.14 2250.49,1260.14 2271.71,1281.35 v1(2271.71,1299.34)
MCU_GPIO0: J1.15 U1.A8 | length 2037.8
  Top Layer w5.66: v1(428.76,1100.18) U1.A8@444.51,1084.43
  L08_SIG3 w4.5: v1(428.76,1100.18) 448,1080.94 448,1027.11 485.17,989.94 561.4,989.94 570.23,981.12 570.23,748.1 560.1,737.98 550.34,737.98 549.09,736.73 548.74,736.73 540,727.99 540,715 532.56,707.56 516.83,707.56 507.5,698.24 507.5,589.77 507.54,589.73 542.93,554.35 542.93,519.07 559.6,502.4 645.16,502.4 763.92,383.64 763.92,326.07 774.2,315.8 774.2,292.63 944.79,122.05 1501.94,122.05 v1(1521.6,102.39)
  Bottom Layer w5.66: v1(1521.6,102.39) 1526.44,97.55 J1.15@1526.44,27.59
MCU_GPIO1: J1.13 U1.A7 | length 3143.6
  Top Layer w5.66: v1(397.27,1100.18) U1.A7@413.01,1084.43
  L08_SIG3 w4.5: v1(1048.57,554.51) 1001.8,554.51 950.28,502.99 950.28,294.71 1005.51,239.48 1423.52,239.48 1483.84,179.16 1483.84,155.77 1494.13,145.48 1512.39,145.48 v1(1558.07,99.8)
  Bottom Layer w5.66: v1(397.27,1100.18) 397.27,1130.91 375.19,1152.99 375.19,1230.38 350.38,1255.19 350.38,1356.54 425.76,1431.92 520.63,1431.92 669.02,1580.3 914.74,1580.3 985,1510.04 985,1148 1017,1116 1017,1000 1029.87,987.13 1029.87,573.21 v1(1048.57,554.51) ; J1.13@1546.12,27.59 1546.12,87.86 v1(1558.07,99.8)
MCU_GPIO2: J1.11 U1.B7 | length 3486.3
  Top Layer w5.66: v1(397.27,1068.68) U1.B7@413.01,1052.94
  L08_SIG3 w4.5: v1(1043.57,481.86) 1043.57,285.43 1059.65,269.35 1439.21,269.35 1474.84,233.72 1635.95,233.72 1682.55,187.13 1682.55,41.83 v1(1565.72,-75)
  Bottom Layer w5.66: v1(397.27,1068.68) 377.39,1088.56 377.39,1131.32 361.8,1146.91 361.8,1227.28 338.72,1250.36 338.72,1361.36 420.93,1443.58 438.02,1443.58 586.44,1592 644.7,1592 ; 644.74,1591.96 919.57,1591.96 1003,1508.53 1003,1156 1029,1130 1029,1009.51 1044,994.51 1044,584.51 1066.4,562.11 1066.4,504.69 1044.12,482.42 1043.01,482.42 v1(1043.57,481.86) ; v1@1565.81,-75 J1.11@1565.81,27.59
MCU_GPIO3: J1.9 U1.C7 | length 2111.7
  Top Layer w5.66: v1(397.27,1037.19) U1.C7@413.01,1021.44
  L08_SIG3 w4.5: v1(397.27,1037.19) 399.94,1034.51 399.75,1034.32 399.75,1027.95 399.94,1027.76 399.94,1024.93 412.77,1012.11 412.77,997.23 420.49,989.51 454.49,989.51 485.12,958.88 531,958.88 538.56,951.32 538.56,747.38 529.16,737.98 517.34,737.98 507.94,728.57 507.94,716.75 497.46,706.28 485.65,706.28 476.44,697.07 476.44,585.07 498.24,563.27 498.24,524.76 535,488 641.71,488 716.13,413.58 716.13,318.51 970.21,64.43 1548.59,64.43 1585.49,101.33 v1(1585.49,101.47)
  Bottom Layer w5.66: J1.9@1585.49,27.59 v1(1585.49,101.47)
MCU_GPIO4: J1.7 U1.D7 | length 2131.8
  Top Layer w5.66: v1(397.27,1005.69) U1.D7@413.01,989.94
  L08_SIG3 w4.5: v1(397.27,1005.69) 381.48,989.91 381.48,968.32 390.92,958.88 447.3,958.88 478.8,927.39 497.23,927.39 507.07,917.55 507.07,746.07 498.54,737.54 485.41,737.54 463.81,715.94 463.81,528.47 520.29,472 621.26,472 682.39,410.88 682.39,252.48 832.32,102.55 v1(895.89,102.55)
  Bottom Layer w5.66: v1(895.89,102.55) 952.45,102.55 971.94,122.05 1590.13,122.05 1605.18,107 J1.7@1605.18,27.59
MCU_GPIO5: J1.5 U1.A6 | length 2809.9
  Top Layer w5.66: U1.A6@381.52,1084.43 364.04,1101.91 364.04,1167.41 332.79,1198.65 332.79,1423.67 v1(384.12,1475)
  L03_SIG1 w4.5: v1(384.12,1475) 399.53,1459.59 490.08,1459.59 693.25,1256.42 693.25,1198.73 648.55,1154.03 648.55,1113.15 717.69,1044 717.69,990.39 727.54,980.54 727.54,868.76 735.51,860.79 810.09,860.79 865.17,805.71 865.17,644.83 889.36,620.64 916.03,620.64 933,603.67 933,564.04 965,532.04 965,470.71 1010.31,425.4 1068.19,425.4 1086.5,443.71 1302.29,443.71 1380.76,365.23 1464.93,365.23 1513.05,317.11 1513.05,316.79 1574.83,255 1589,255 1640.1,203.9 v1(1640.1,116.53)
  Bottom Layer w5.66: J1.5@1624.86,27.59 1624.86,101.29 v1(1640.1,116.53)
MCU_GPIO6: R88.2 R91.2 U1.B6 | length 167.4
  Top Layer w5.66: v1(365.77,1068.68) U1.B6@381.52,1052.94
  Bottom Layer w5.66: R88.2@296.63,1161.2 R91.2@337.63,1161.2 339.17,1159.66 339.17,1135.77 339.17,1135.47 350.02,1124.62 350.02,1084.43 v1(365.77,1068.68)
MCU_GPIO7: R94.2 R96.2 U1.C6 | length 415.1
  Top Layer w5.66: R96.2@141.08,1111.89 132.34,1120.63 132.34,1149.72 141.32,1158.7 141.32,1170.51 R94.2@142.26,1170.51 145.25,1173.5 v1(145.25,1197.65) v1@145.25,1202.65 ; v1(365.77,1037.19) U1.C6@381.52,1021.44
  L03_SIG1 w4.5: v1@143.25,1202.65 145.25,1202.65 v1@147.75,1200.15 ; v1(145.25,1197.65) 205.31,1197.65 v1(365.77,1037.19)
MCU_GPIO8: R55.2 R83.2 U1.D6 | length 260.5
  Top Layer w5.66: v1(365.77,1005.69) U1.D6@381.52,989.94
  Bottom Layer w5: 350.04,1062.85 350.04,1021.42 v1(365.77,1005.69)
  Bottom Layer w5.66: R55.2@214.63,1161.2 R83.2@255.63,1161.2 ; R83.2@255.63,1157.26 350.04,1062.85
MCU_GPIO9: J1.73 LED4.2 U1.A5 | length 5831.9
  Top Layer w5.66: U1.A5@350.02,1084.43 350.02,1157.57 320.71,1186.88 320.71,1469.85 v1(410.14,1559.28) ; LED4.2@2193.68,1169.19 2212.25,1169.19 v1(2242.64,1138.8)
  L08_SIG3 w4.5: v1(410.14,1559.28) 425.86,1575 485,1575 687.03,1777.03 1008.71,1777.03 1048.82,1817.14 1590.71,1817.14 1682.78,1725.08 1802.86,1725.08 1854.13,1673.81 2132.67,1673.81 2179.48,1627 2229.19,1627 2259.07,1597.12 2277.24,1597.12 2294.22,1580.14 2294.22,1190.39 v1(2242.64,1138.8) 2242.64,1138.39 2257.33,1123.71 2271.97,1123.71 2288.8,1106.87 2288.8,818.85 2211.73,741.78 2211.73,289.73 2024.8,102.8 2024.8,5.08 1907.75,-111.97 810.72,-111.97 v1(758.41,-59.66)
  Bottom Layer w5.66: v1(758.41,-59.66) 758.54,-59.54 J1.73@758.54,27.53
MCU_GPIO10: J1.64 R3.1 U1.C5 | length 5382.1
  Top Layer w5.66: v1(334.27,1037.19) U1.C5@350.02,1021.44 ; R3.1@1790.75,596.45 1790.75,553.22 v1(1792.41,551.56)
  L03_SIG1 w4.5: v1(856.32,338.46) 856.32,165.88 953.53,68.67 1393.67,68.67 v1(1412.21,87.21)
  L05_SIG2 w4: v1(153.43,1143.06) 243.64,1233.28 243.64,1397.92 369.93,1524.2 500.2,1524.2 587.67,1611.67 1782.33,1611.67 1947.8,1446.2 1947.8,570.8 1910.63,533.63 1840.29,533.63 1822.36,551.56 v1(1792.41,551.56) 1792.41,534.59 1855,472 1855,209 1740,94 1709.65,94 1565.79,-49.86 1535,-49.86 1529.76,-55.1 1498.97,-55.1 1487.99,-44.13 1487.99,11.42 v1(1412.21,87.21)
  Bottom Layer w5.66: v1(153.43,1143.06) 176.24,1120.25 176.24,1105.96 205.63,1076.57 294.89,1076.57 v1(334.27,1037.19) ; v1(856.32,338.46) 856.68,338.11 856.68,253.54 J1.64@857.03,253.19
MCU_GPIO11: J3.116 U1.A4 | length 2803.6
  Top Layer w5.66: U1.A4@318.53,1084.43 318.53,1141.63 294.6,1165.56 294.6,1513.6 485.18,1704.18 v1(530.18,1704.18)
  L03_SIG1 w4.5: v1(530.18,1704.18) 552,1726 625.86,1726 628.11,1726 ccw(c628.11,1739.75) 641.86,1739.75 641.86,1745 cw(c655.61,1745) 669.36,1745 669.36,1709.75 ccw(c683.11,1709.75) 696.86,1709.75 696.86,1745 cw(c710.61,1745) 724.36,1745 724.36,1709.75 ccw(c738.11,1709.75) 751.86,1709.75 751.86,1712.25 cw(c765.61,1712.25) 765.61,1726 785,1726 1323.48,1726 1351.48,1754 1536.58,1754 1639.58,1651 1850.03,1651 1883.69,1617.34 2217.19,1617.34 v1(2239.84,1594.69)
  Bottom Layer w5.66: J3.116@2178.19,1594.78 2239.75,1594.78 v1(2239.84,1594.69)
MCU_GPIO12: J1.16 U1.A3 | length 2828.1
  Top Layer w5.66: U1.A3@287.03,1084.43 287.03,1122.28 270.19,1139.12 270.19,1560.27 302,1592.08 v1(302,1614)
  L03_SIG1 w4.5: v1(302,1614) 321.64,1633.64 461.26,1633.64 498.61,1596.29 498.61,1499.89 731.37,1267.13 731.37,1210.48 673.45,1152.55 673.45,1110.97 730.32,1054.1 730.32,1039.42 747.41,1022.32 791.07,1022.32 797.22,1028.47 836.21,1028.47 847.08,1017.6 847.08,920.18 876.85,890.42 952.8,890.42 1014,829.22 1014,678.58 1094.2,598.38 1319.62,598.38 1385,533 1385,470.73 v1(1531.36,324.37)
  Bottom Layer w5.66: J1.16@1526.44,253.19 1526.44,306.95 1531.36,311.87 v1(1531.36,324.37)
MCU_GPIO13: J1.14 U1.A2 | length 2902.8
  Top Layer w5.66: v1(238.12,1597.36) 238.12,1124.8 255.53,1107.4 U1.A2@255.53,1084.43
  L03_SIG1 w4.5: v1(238.12,1597.36) 238.12,1620.62 266.84,1649.34 471.2,1649.34 516.3,1604.24 516.3,1503.43 744,1275.73 744,1205.25 702.68,1163.92 702.68,1132.47 742.76,1092.39 742.76,1064.5 754.31,1052.95 838.1,1052.95 861.23,1029.81 861.23,932.87 885.65,908.45 967.93,908.45 1031.15,845.23 1031.15,685.48 1101.3,615.32 1325.68,615.32 1410.91,530.09 1410.91,493.25 1558.24,345.91 v1(1558.24,321.57)
  Bottom Layer w5.66: J1.14@1546.12,253.19 1546.12,309.45 v1(1558.24,321.57)
MCU_GPIO14: J2.59 U1.B3 | length 1368.4
  Top Layer w5.66: v1(270.42,1597.36) 257.82,1584.77 257.82,1130.41 271.28,1116.95 271.28,1068.68 U1.B3@287.03,1052.94
  L08_SIG3 w4.5: v1(37.89,1040) 23.32,1054.57 23.32,1468.16 62.35,1507.19 222.19,1507.19 270.42,1555.42 v1(270.42,1597.36)
  Bottom Layer w5.66: J2.59@12.41,1063.37 35.22,1063.37 37.89,1060.7 v1(37.89,1040)
MCU_GPIO15: J1.68 U1.C4 | length 4022.6
  Top Layer w5.66: v1(302.78,1037.19) U1.C4@318.53,1021.44
  L08_SIG3 w4.5: v1(833.94,357.05) 833.94,356.9 817.62,340.59 817.62,300.88 919.5,199 1335,199 1384,150 1408.74,150 1421.83,163.09 v1(1423.87,163.09)
  L05_SIG2 w4: v1(302.78,1037.19) 302.78,1182.03 307.08,1186.33 307.08,1339.5 400.55,1432.97 401.7,1432.97 ; 401.71,1432.99 523.96,1432.99 585.52,1494.55 899.64,1494.55 925.1,1469.08 925.1,1466.84 928.94,1463 1218,1463 1286.91,1394.09 1286.91,1376.28 1320.1,1343.08 1322.02,1343.08 1349.41,1315.69 1349.41,1279.93 1405.03,1224.31 1410.89,1224.31 1526.84,1108.36 1526.84,1076.4 1539.24,1064 1539.3,1064 1539.44,1063.86 1553.61,1063.86 1553.75,1064 1618.5,1064 1627.15,1055.35 1627.15,1003.71 1542.8,919.36 1542.8,509.8 1454.66,421.66 1432.6,421.66 1418.83,435.43 1387.43,435.43 1373.2,421.2 1373.2,386.9 1376.9,383.2 1376.9,382.92 1386.92,372.9 1387.2,372.9 1388.02,372.08 1490.92,372.08 1516,347 1516,230.28 1448.72,163 1421.96,163 v1@1421.87,163.09
  Bottom Layer w5.66: 817.62,337.51 817.62,340.73 v1(833.94,357.05) ; J1.68@817.64,253.21 817.64,337.49
MCU_GPIO16: R81.2 R84.2 U1.D5 | length 266
  Top Layer w5.66: R81.2@138.91,986.52 139.11,986.72 v1(174.14,986.72) ; R84.2@141,946.24 R81.2@141,986.62 ; v1(334.27,1005.69) U1.D5@350.02,989.94
  Bottom Layer w5: v1(174.14,986.72) 198.89,986.72 202.37,990.19 318.77,990.19 v1(334.27,1005.69)
MCU_GPIO17: J1.10 U1.B2 | length 2977.5
  Top Layer w5.66: v1(216.58,1562.09) 225,1553.66 225,1112.58 239.79,1097.8 239.79,1068.68 U1.B2@255.53,1052.94
  L03_SIG1 w4.5: v1(216.58,1562.09) 216.58,1628.75 255.6,1667.77 470.62,1667.77 536.18,1602.21 536.18,1535.37 759.37,1312.18 759.37,1249.48 771.15,1237.71 772.46,1237.71 782.56,1227.6 782.56,1213.31 772.46,1203.21 769.72,1203.21 758.81,1192.3 748.91,1192.3 725.72,1169.11 725.72,1134.63 756.08,1104.27 808.7,1104.27 882,1030.97 882,986.76 932.76,936 971.82,936 1048.57,859.25 1048.57,697.53 1108.76,637.34 1329.66,637.34 1454,513 1454,475.07 1584.04,345.03 1584.04,335.8 v1(1586.21,333.62)
  Bottom Layer w5.66: J1.10@1585.49,253.19 1585.85,253.55 1585.85,333.26 v1(1586.21,333.62)
MCU_GPIO18: J1.66 R23.1 U1.F2 | length 5341.4
  Top Layer w5.66: v1(239.79,942.7) U1.F2@255.53,926.95 ; v1@1750.74,558.04 R23.1@1750.74,596.45
  L03_SIG1 w4.5: v1(836.69,309.45) 836.69,140.1 921.42,55.37 1411.82,55.37 1505.2,-38 v1(1507,-38)
  L05_SIG2 w4: v1@175.89,1028.26 159.9,1044.25 155.33,1048.82 155.33,1116.33 159.9,1120.9 174.77,1135.77 256.08,1217.08 256.08,1395.93 374.15,1514 509,1514 594.3,1599.3 1778.88,1599.3 1937.6,1440.58 1937.6,577.6 1903.83,543.83 1857.17,543.83 1828,573 1767.1,573 v1(1751.44,557.34) 1731.55,537.45 1683.27,537.45 1644,498.18 1644,402 1739.44,306.56 1739.44,262.5 1721.11,244.17 1721.11,217.47 1616,112.36 1616,51 1527,-38 v1(1507,-38)
  Bottom Layer w5.66: v1@175.89,1028.26 157.51,1009.88 157.51,961.99 176.79,942.7 v1(239.79,942.7) ; v1@837.02,309.45 837.02,253.52 J1.66@837.34,253.19
  other v1: 173.89,1028.26
MCU_GPIO19: J2.54 U1.B1 | length 767
  Top Layer w5.66: v1(-274.84,1122.51) -145.26,1252.1 144.9,1252.1 190.16,1206.84 190.16,1135.77 190.16,1086.81 U1.B1@224.04,1052.94
  Bottom Layer w5.66: v1(-274.84,1122.51) -274.75,1122.42 J2.54@-213.19,1122.42
MCU_GPIO20: J1.8 U1.C1 | length 2588.7
  Top Layer w5.66: v1(208.29,1037.19) U1.C1@224.04,1021.44
  L08_SIG3 w4.5: v1(208.29,1037.19) 192.58,1021.48 192.58,966.42 200.52,958.48 309.22,958.48 318.53,949.17 318.53,936.23 327.78,926.97 371.66,926.97 381.29,917.34 381.29,905.52 391.35,895.47 435.53,895.47 449,882 449,748 439.06,738.06 422.94,738.06 413.33,728.45 413.33,653.02 435,631.34 435,484.35 498.35,421 630.07,421 651.69,399.38 651.69,138.39 765.68,24.4 1582.86,24.4 1624.79,66.32 1624.79,128.13 1630.31,133.66 1630.31,146.34 1612.86,163.8 v1(1611.47,163.8)
  Bottom Layer w5.66: J1.8@1605.18,253.19 1603.41,251.42 1603.41,175.2 1611.47,167.13 v1(1611.47,163.8)
MCU_GPIO21: J1.6 U1.C2 | length 2464.4
  Top Layer w5.66: v1(239.79,1037.19) U1.C2@255.53,1021.44
  L08_SIG3 w4.5: 229.68,988.81 224,994.49 224,1021.4 v1(239.79,1037.19) ; 231.19,988.81 231.3,988.7 308.78,988.7 309.48,988 309.57,988 318.53,979.04 318.53,967.72 327.77,958.48 371.64,958.48 381.28,948.84 381.28,937.03 391.32,926.99 460.01,926.99 476.44,910.56 476.44,747.9 451.19,722.65 451.19,517.95 516.64,452.5 616.43,452.5 665.55,403.37 665.55,187.03 809.48,43.1 1553.03,43.1 1606.55,96.63 1606.55,119.02 1593.16,132.41 1593.16,185.97 1600.66,193.47 1619.6,193.47 v1(1621.24,191.83)
  Bottom Layer w5.66: v1(1621.24,191.83) 1623.05,193.65 1623.05,251.38 J1.6@1624.86,253.19
MCU_GPIO22: J1.62 R24.1 U1.F1 | length 5033
  Top Layer w5.66: v1(171.68,1069.32) 191.3,1049.7 191.3,959.69 U1.F1@224.04,926.95 ; R24.1@1710.74,596.45 1710.74,558.04 v1(1711.44,557.34)
  L03_SIG1 w4.5: v1(877.66,309.45) 877.66,164.49 957.14,85 1330.13,85 1362.13,117 1429.32,117 v1@1441.11,105.21
  L05_SIG2 w4: v1(171.68,1069.32) 171.68,1108.63 266.28,1203.23 266.28,1391.7 377.58,1503 516,1503 602.1,1589.1 1774.65,1589.1 1927.4,1436.35 1927.4,583.41 1898.02,554.03 1861.39,554.03 1828.04,587.38 1741.48,587.38 v1(1711.44,557.34) ; v1(1441.11,104.21) 1474.9,138 1545.19,138 1671.19,264 1717,264 1726.1,273.1 1726.1,293.5 1626,393.6 1626,512 1672.04,558.04 v1@1710.74,558.04
  Bottom Layer w5.66: J1.62@877.98,253.52 v1@877.98,309.45
MCU_GPIO23: J1.75 LED3.2 U1.B8 | length 6432.1
  Top Layer w5.66: v1(428.76,1068.68) U1.B8@444.51,1052.94 ; LED3.2@2189.55,1055.99 2220.56,1055.99 v1(2235.62,1040.92)
  L05_SIG2 w4: v1(428.76,1068.68) 442.86,1082.78 442.86,1253.16 523.1,1333.39 709.05,1333.39 848.34,1194.1 936.7,1194.1 989.86,1140.94 989.86,1005.14 1047,948 1145.99,948 1323.52,1125.54 1458.28,1125.54 1488,1095.82 1488,1079 1409,1000 1409,507 1350.8,448.8 1350.8,376.55 1385.26,342.09 1458.91,342.09 1491,310 1491,263 1474.34,246.34 1399.41,246.34 1372.01,218.94 1372.01,141.46 1390,123.48 1390,53.92 1371.34,35.26 1371.34,14.84 1387.22,-1.04 1387.22,-77.78 1349.7,-115.3 895.3,-115.3 799.96,-19.96 753.5,-19.96 v1(738.44,-35.02)
  Bottom Layer w5.66: J1.75@738.92,27.59 738.68,27.35 738.68,-34.78 v1(738.44,-35.02) 738.44,-64.91 791.76,-118.22 1866.09,-118.22 2090,105.69 2090,985 2130,1025 2219.7,1025 v1(2235.62,1040.92)
MCU_GPIO24: J3.100 U1.C8 | length 2419.9
  Top Layer w5.66: v1(428.76,1037.19) U1.C8@444.51,1021.44
  L03_SIG1 w4.5: v1(622.51,1574.17) 643.03,1594.69 1800.37,1594.69 1948.36,1446.7 2230.27,1446.7 v1(2239.84,1437.21) v1(2239.84,1437.21)
  L08_SIG3 w4.5: v1(428.76,1037.19) 426.27,1039.68 426.27,1050.67 415.97,1060.97 413.26,1063.68 413.26,1135.77 413.26,1236.18 468,1290.92 468,1444.87 597.3,1574.17 v1(622.51,1574.17)
  Bottom Layer w5.66: J3.100@2178.19,1437.3 2239.75,1437.3 v1(2239.84,1437.21)
MCU_GPIO25: J3.113 U1.D8 | length 2452
  Top Layer w5.66: v1(428.76,1005.69) U1.D8@444.51,989.94
  L08_SIG3 w4.5: v1(428.76,1005.69) 426.6,1007.85 426.6,1016.86 412.92,1030.54 412.92,1046.08 405,1054 390.29,1054 381.55,1062.74 381.55,1207.81 357.67,1231.7 357.67,1423.67 694.6,1760.6 1034.22,1760.6 1073.32,1799.71 1586.29,1799.71 1673.74,1712.26 1797.14,1712.26 1880.75,1628.65 1980.28,1628.65 v1(2014.24,1594.69)
  Bottom Layer w5.66: J3.113@1952.59,1575.1 2006.1,1575.1 2013.6,1582.6 2013.6,1594.05 v1(2014.24,1594.69)
MCU_GPIO26: J1.4 U1.B9 | length 2752
  Top Layer w5.66: U1.B9@476.01,1052.94 v1(491.75,1068.68)
  L08_SIG3 w4.5: v1(1206.9,379.5) 1216.78,369.61 1221.03,365.37 1268.63,365.37 1287.12,346.88 1446.97,346.88 1507.6,286.24 1616.04,286.24 v1(1644.64,314.84)
  Bottom Layer w5.66: v1(491.75,1068.68) 491.75,1111.4 524,1143.65 524,1418.8 673.85,1568.64 909.91,1568.64 970,1508.55 970,1139.41 1000.19,1109.21 1000.19,998.21 993.32,991.34 993.32,570.68 1025.43,538.57 1025.43,474.78 1038.7,461.51 1053.19,461.51 ; 1053.22,461.54 1087.84,461.54 1088.38,461 1123,461 1204.5,379.5 v1(1206.9,379.5) ; J1.4@1644.55,253.19 1644.55,314.75 v1(1644.64,314.84)
MCU_GPIO27: J1.3 U1.C9 | length 3271.5
  Top Layer w5.66: U1.C9@476.01,1021.44 v1(491.75,1037.19)
  L08_SIG3 w4.5: v1(1007.6,519.85) 1059.36,519.85 1066.67,512.54 1066.67,463.54 1078.92,451.3 1078.92,436.12 1072.45,429.66 1072.45,309.95 1099.1,283.3 1450.86,283.3 1487.81,246.34 1641.18,246.34 1704.6,182.92 1704.6,25.4 1644.46,-34.75 v1(1644.46,-75)
  Bottom Layer w5: v1(491.75,1037.19) 507.75,1053.18 507.75,1092.38
  Bottom Layer w5.66: 507.75,1092.38 507.75,1101.75 538.96,1132.96 538.96,1417.27 675.85,1554.15 907.91,1554.15 958.34,1503.72 958.34,1129.66 988.53,1099.47 988.53,1003.04 981.66,996.17 981.66,545.79 v1(1007.6,519.85) ; v1(1644.46,-75) J1.3@1644.55,27.59
MCU_GPIO28: J1.1 U1.D9 | length 3024.2
  Top Layer w5.66: U1.D9@476.01,989.94 v1(491.75,1005.69)
  L08_SIG3 w4.5: v1(1002.47,474.88) 1002.47,303.53 1053.9,252.1 1428.75,252.1 1428.9,251.95 1432.41,251.95 1467.76,216.6 1629.04,216.6 1664.23,181.41 v1(1664.23,101.47)
  Bottom Layer w5: v1(491.75,1005.69) 507.25,1021.19 529.17,1021.19 538.96,1030.98 538.96,1086.96
  Bottom Layer w5.66: 538.96,1086.96 538.96,1111.95 552.09,1125.08 552.09,1413.35 681.24,1542.49 903.08,1542.49 945.69,1499.88 945.69,1153.31 946,1153 946,1121.37 976.87,1090.49 976.87,1007.87 970,1001 970,507.36 v1(1002.47,474.88) ; J1.1@1664.23,27.59 v1(1664.23,101.47)
MCU_GPIO29: J3.107 U1.A9 | length 2307.2
  Top Layer w5.66: U1.A9@476.01,1084.43 441.72,1118.71 396.26,1118.71 375.7,1139.28 375.7,1172.24 344.45,1203.48 344.45,1401.24 401.95,1458.74 401.95,1494.67 426.88,1519.61 450.22,1519.61 482.29,1551.68 540.53,1551.68 621.45,1632.6 642.05,1632.6 719.96,1710.5 987.66,1710.5 1073.84,1796.69 1264.73,1796.69 v1(1284.53,1776.89)
  Bottom Layer w5.66: v1(1284.53,1776.89) 1312.62,1748.75 1647.23,1748.75 1879.94,1516.04 J3.107@1952.59,1516.04
MCU_GPIO30: J3.109 U1.A10 | length 2296.6
  Top Layer w5.66: U1.A10@507.5,1084.43 460.09,1131.85 399.62,1131.85 387.36,1144.11 387.36,1177.07 356.11,1208.31 356.11,1390.35 413.61,1447.84 413.61,1489.84 429.13,1505.36 452.47,1505.36 487.12,1540.02 545.36,1540.02 624.34,1619 644.94,1619 724.79,1698.84 992.49,1698.84 1076.88,1783.23 1229.47,1783.23 1253.64,1759.06 1312.49,1759.06 v1(1320.01,1766.58)
  Bottom Layer w5.66: v1(1320.01,1766.58) 1651.79,1766.58 1715.71,1702.66 1773.34,1645.03 1882.64,1535.73 J3.109@1952.59,1535.73
MCU_GPIO31: J2.50 U1.B10 | length 1706.2
  Top Layer w5.66: U1.B10@507.5,1052.94 v1(523.25,1068.68) 523.25,1118.93 601.99,1197.68 601.99,1277.99 v1(611,1287)
  L03_SIG1 w4.5: v1(-278.75,1162.41) -356,1239.66 -356,1374.86 -305.23,1425.63 -230.37,1425.63 -141.57,1514.43 252.42,1514.43 252.48,1514.37 265.22,1514.37 348.59,1431 444.78,1431 588.78,1287 v1(611,1287)
  Bottom Layer w5.66: v1(-278.75,1162.41) -278.13,1161.79 J2.50@-213.19,1161.79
